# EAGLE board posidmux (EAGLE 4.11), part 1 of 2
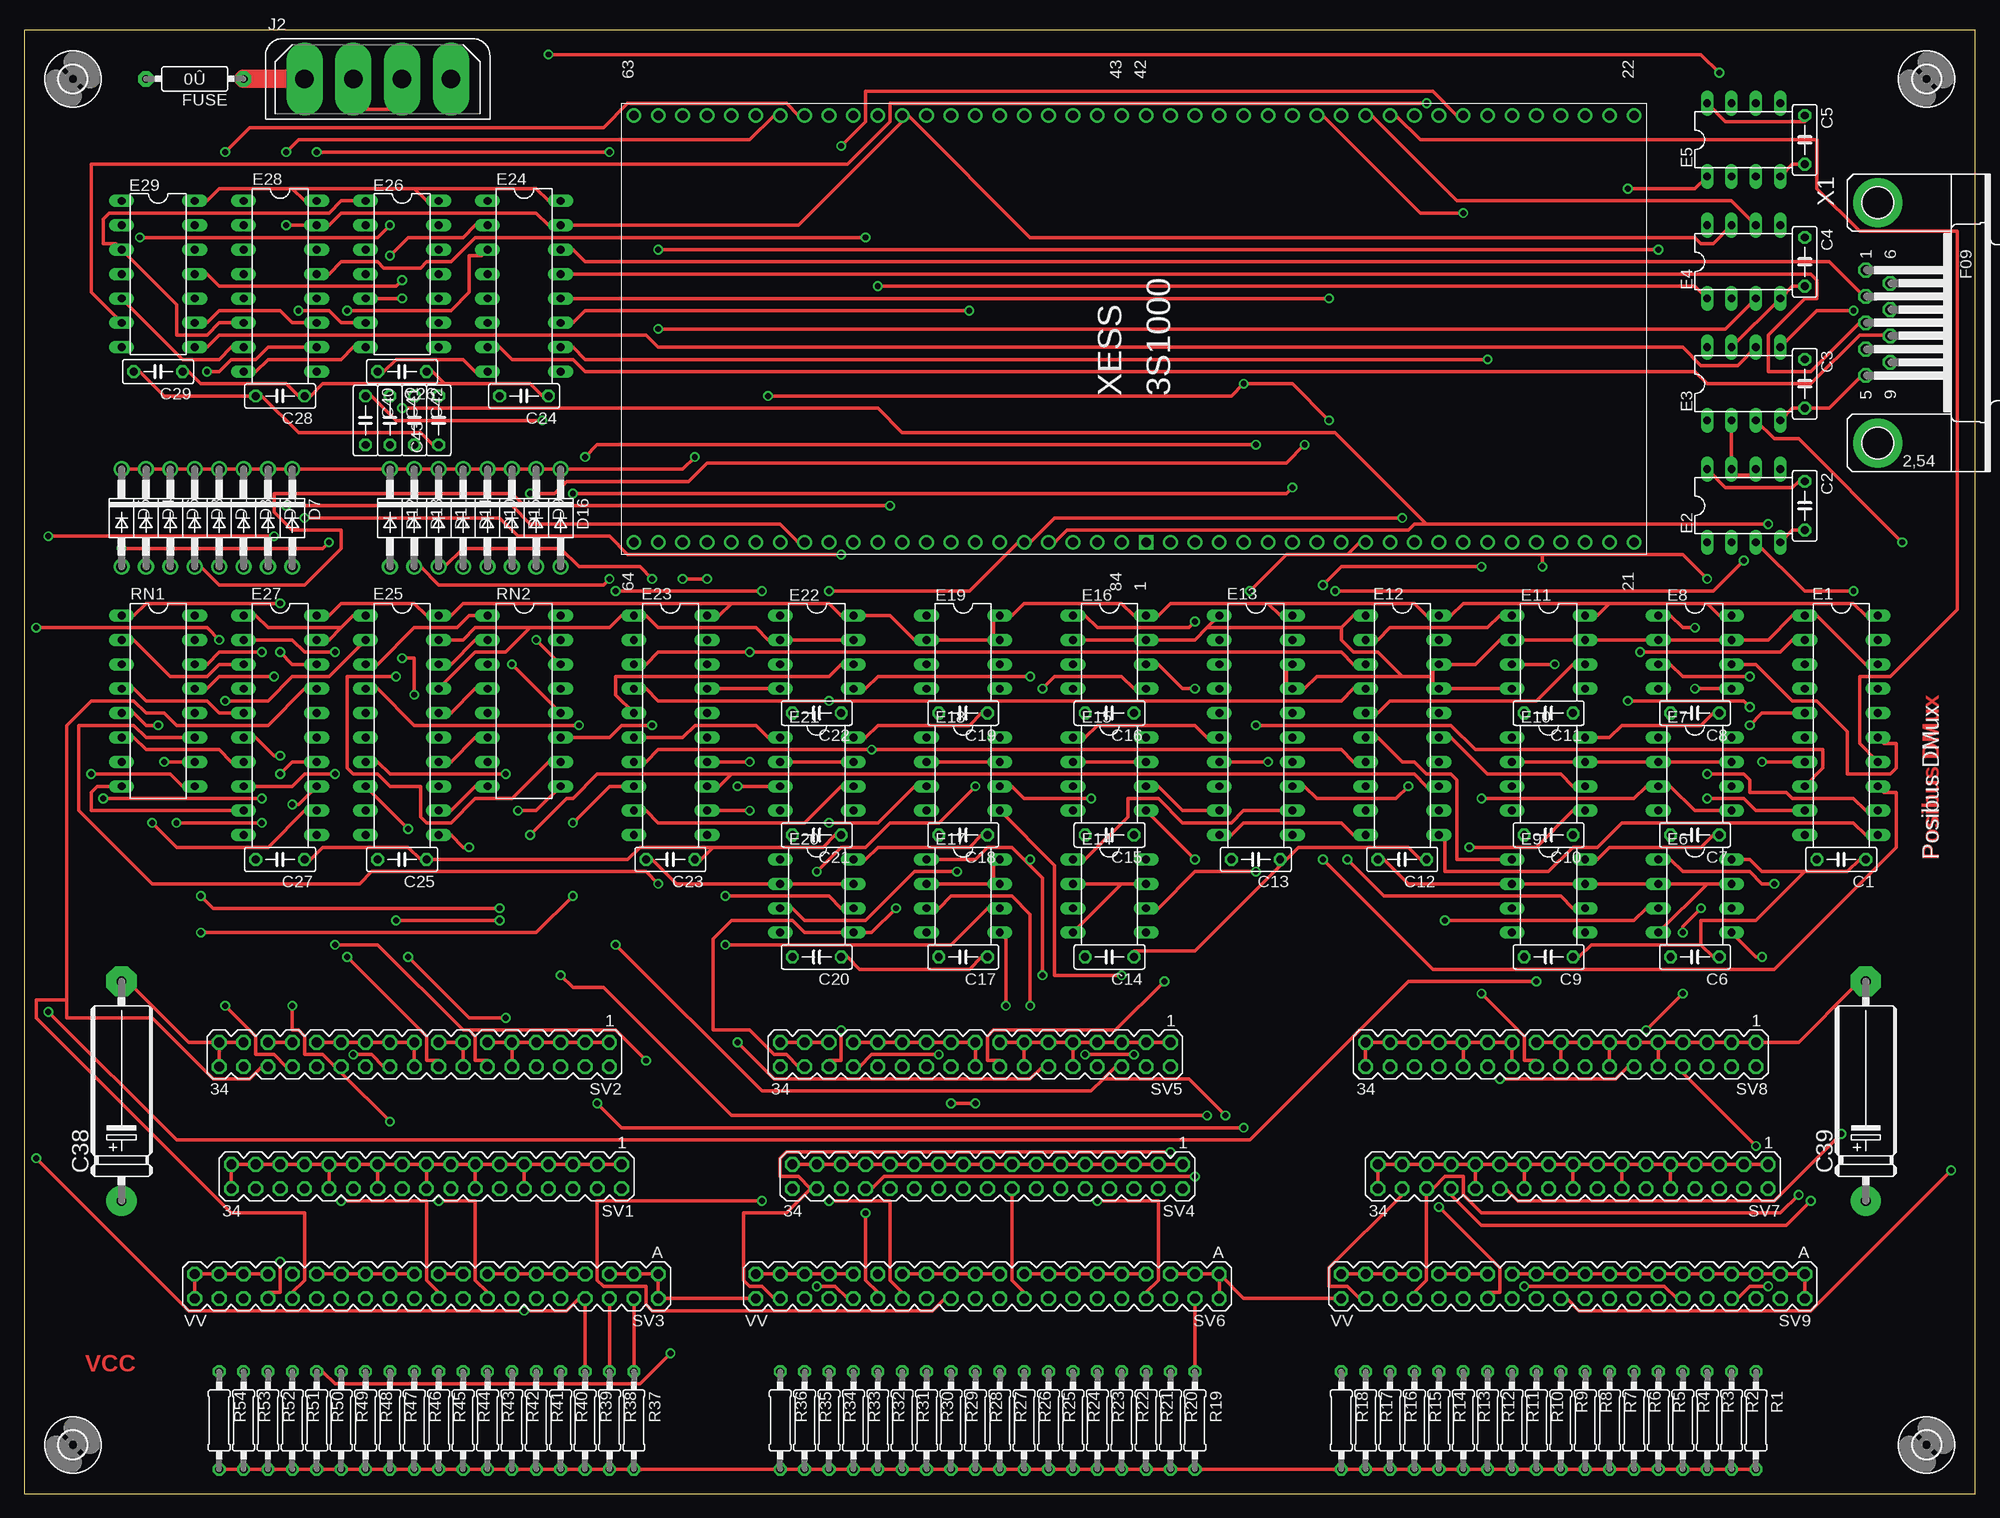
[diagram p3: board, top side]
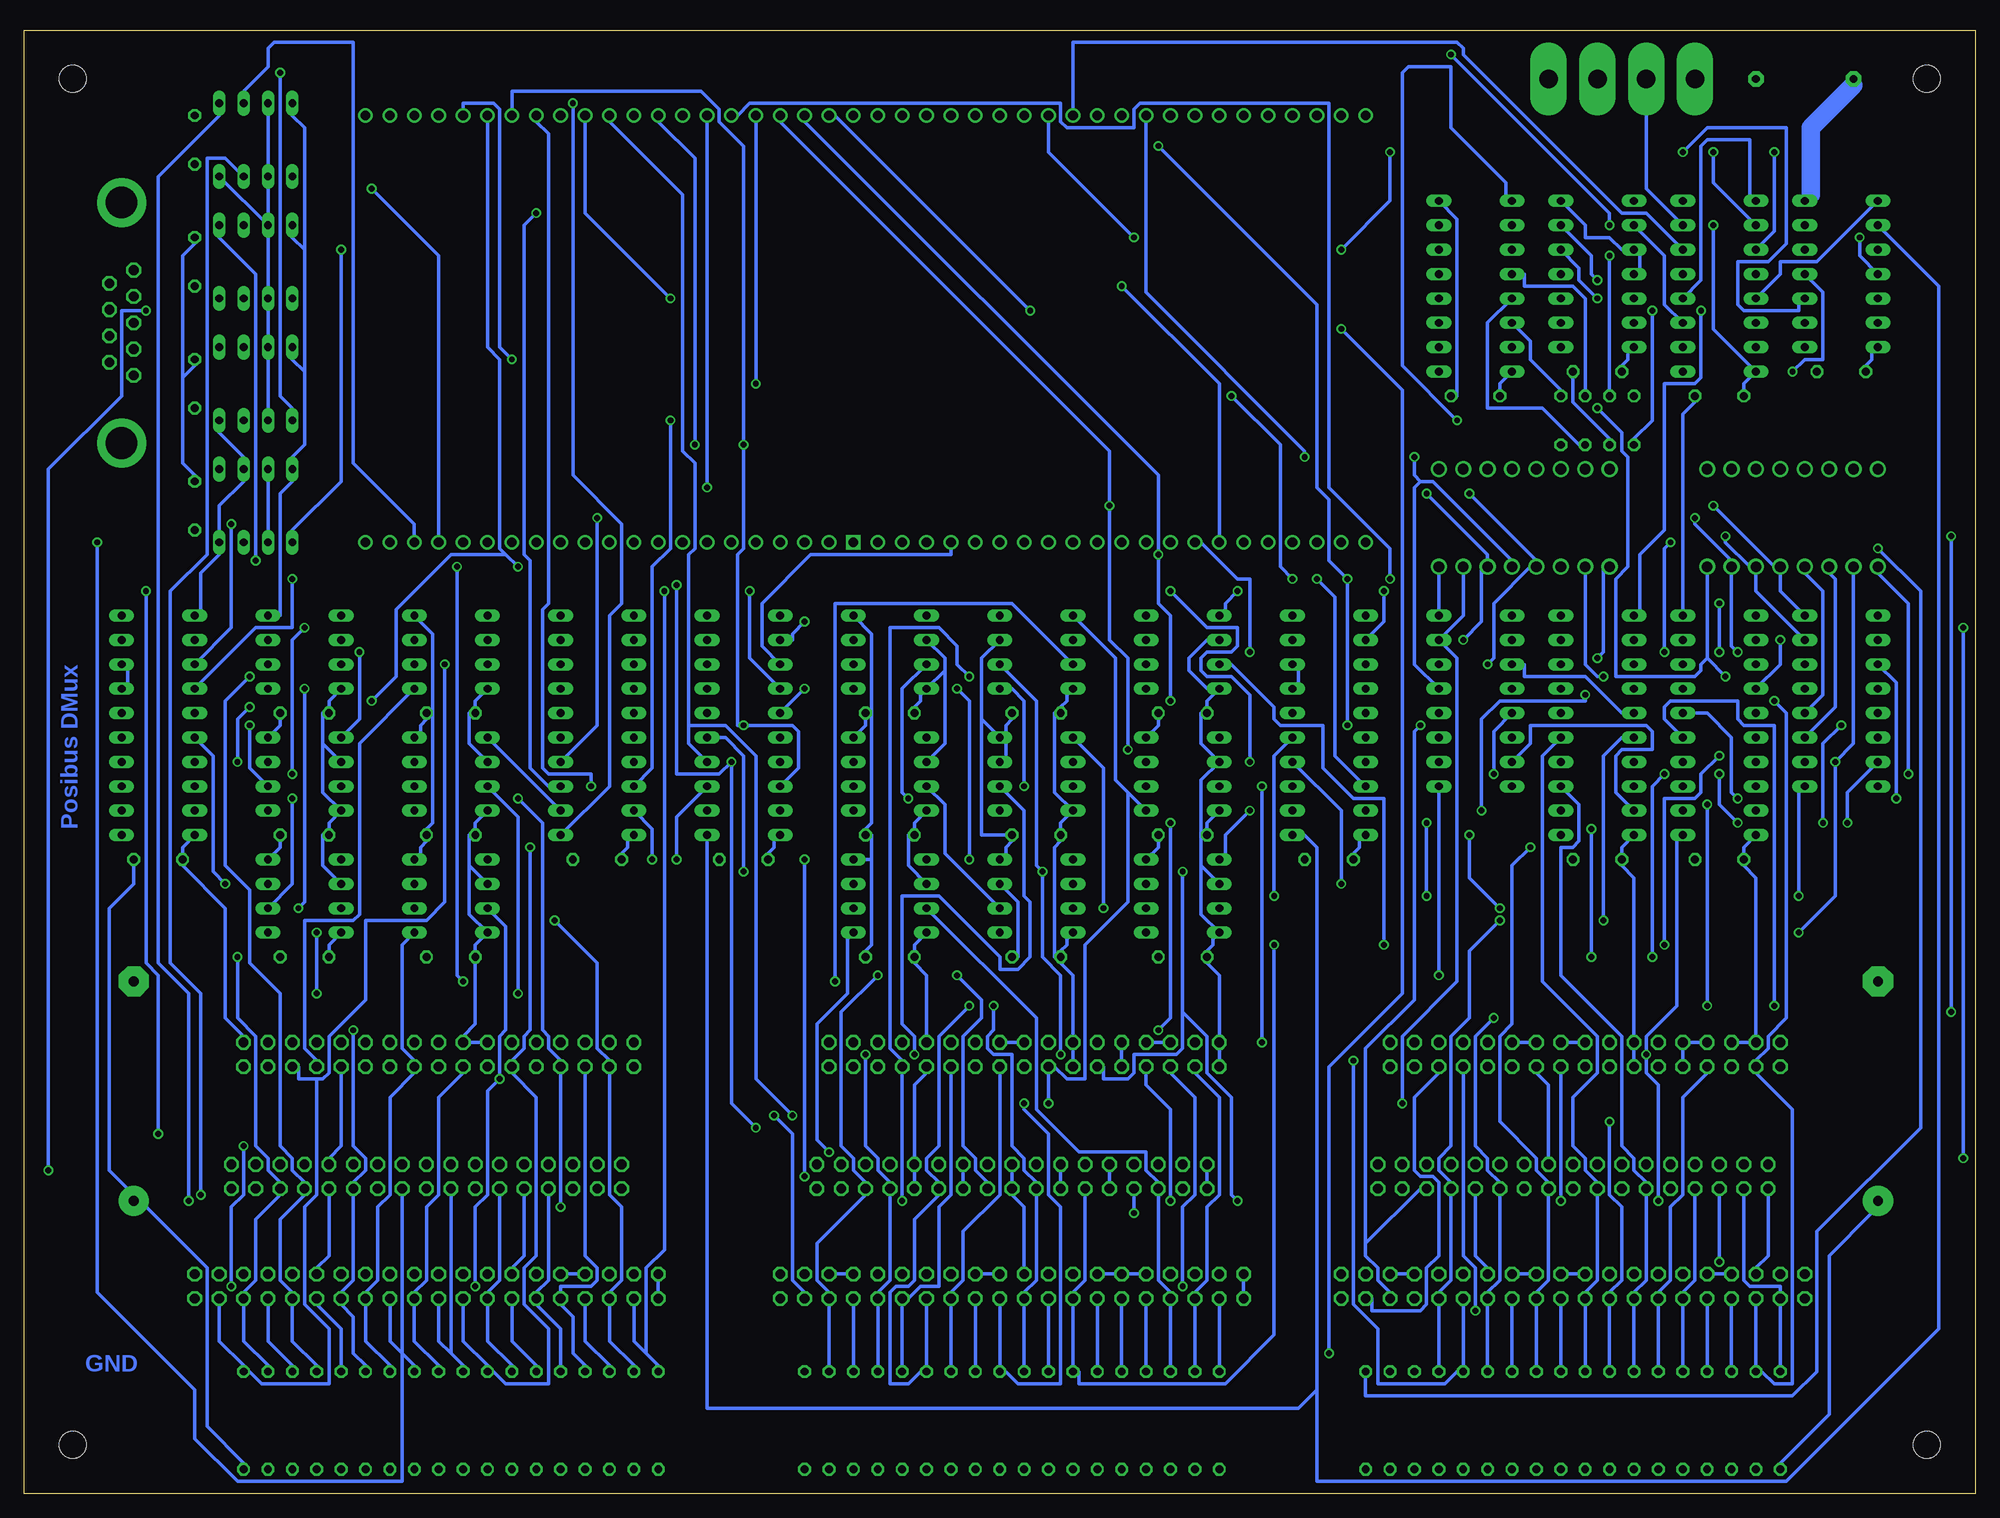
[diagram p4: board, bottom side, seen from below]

Size 203.2 x 152.4 mm. Coordinates in mm from the lower left corner, seen from the top.
Outline: 0,0 203.2,0 203.2,152.4 0,152.4 0,0
Copper layers (1*16): Top 0.035mm / dielectric 1.5mm / Bottom 0.035mm
Design rules "olimex10mil": minimum track width 15mil, minimum drill 24mil, track to track 15mil, track to pad 10mil, pad to pad 10mil, via to via 10mil, smd to smd 10mil, copper to edge 25mil, drill to drill 10mil, minimum pad ring 10mil, minimum via ring 8mil, stop-mask expansion 0mil, vias tented up to drill 0mil, thermal gap 10mil
Net classes: 1 Supply: width 1.905 mm, drill 0.508 mm

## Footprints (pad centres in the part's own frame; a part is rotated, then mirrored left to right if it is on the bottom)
C050-025X075 = drill 0.813 octagon: 1 -2.54,0; 2 2.54,0
E22-6 = drill 1.016 pad 3.15 round: + -11.43,0 | drill 1.016 pad 3.15 octagon: - 11.43,0
DO41-10 = drill 1.118 round: A 5.08,0; C -5.08,0
DIL20 = drill 0.813 long: 1 -11.43,-3.81; 2 -8.89,-3.81; 3 -6.35,-3.81; 4 -3.81,-3.81; 5 -1.27,-3.81; 6 1.27,-3.81; 7 3.81,-3.81; 8 6.35,-3.81; 9 8.89,-3.81; 10 11.43,-3.81; 11 11.43,3.81; 12 8.89,3.81; 13 6.35,3.81; 14 3.81,3.81; 15 1.27,3.81; 16 -1.27,3.81; 17 -3.81,3.81; 18 -6.35,3.81; 19 -8.89,3.81; 20 -11.43,3.81
DIL08 = drill 0.813 long: 1 -3.81,-3.81; 2 -1.27,-3.81; 3 1.27,-3.81; 4 3.81,-3.81; 5 3.81,3.81; 6 1.27,3.81; 7 -1.27,3.81; 8 -3.81,3.81
DIL16 = drill 0.813 long: 1 -8.89,-3.81; 2 -6.35,-3.81; 3 -3.81,-3.81; 4 -1.27,-3.81; 5 1.27,-3.81; 6 3.81,-3.81; 7 6.35,-3.81; 8 8.89,-3.81; 9 8.89,3.81; 10 6.35,3.81; 11 3.81,3.81; 12 1.27,3.81; 13 -1.27,3.81; 14 -3.81,3.81; 15 -6.35,3.81; 16 -8.89,3.81
DIL14 = drill 0.813 long: 1 -7.62,-3.81; 2 -5.08,-3.81; 3 -2.54,-3.81; 4 0,-3.81; 5 2.54,-3.81; 6 5.08,-3.81; 7 7.62,-3.81; 8 7.62,3.81; 9 5.08,3.81; 10 2.54,3.81; 11 0,3.81; 12 -2.54,3.81; 13 -5.08,3.81; 14 -7.62,3.81
0R/10 = drill 0.813 pad 1.6 octagon: 1 -5.08,0; 2 5.08,0
FLOPPY-4 = drill 1.93 pad 3.81 long: 1 7.62,0; 2 2.54,0; 3 -2.54,0; 4 -7.62,0
0207/10 = drill 0.813 octagon: 1 -5.08,0; 2 5.08,0
MA17-2 = drill 1.016 octagon: 1 -20.32,-1.27; 2 -20.32,1.27; 3 -17.78,-1.27; 4 -17.78,1.27; 5 -15.24,-1.27; 6 -15.24,1.27; 7 -12.7,-1.27; 8 -12.7,1.27; 9 -10.16,-1.27; 10 -10.16,1.27; 11 -7.62,-1.27; 12 -7.62,1.27; 13 -5.08,-1.27; 14 -5.08,1.27; 15 -2.54,-1.27; 16 -2.54,1.27; 17 0,-1.27; 18 0,1.27; 19 2.54,-1.27; 20 2.54,1.27; 21 5.08,-1.27; 22 5.08,1.27; 23 7.62,-1.27; 24 7.62,1.27; 25 10.16,-1.27; 26 10.16,1.27; 27 12.7,-1.27; 28 12.7,1.27; 29 15.24,-1.27; 30 15.24,1.27; 31 17.78,-1.27; 32 17.78,1.27; 33 20.32,-1.27; 34 20.32,1.27
DEC40PIN = drill 1.016 octagon: A -24.13,-1.27; AA 3.81,-1.27; B -24.13,1.27; BB 3.81,1.27; C -21.59,-1.27; CC 6.35,-1.27; D -21.59,1.27; DD 6.35,1.27; E -19.05,-1.27; EE 8.89,-1.27; F -19.05,1.27; FF 8.89,1.27; H -16.51,-1.27; HH 11.43,-1.27; J -16.51,1.27; JJ 11.43,1.27; K -13.97,-1.27; KK 13.97,-1.27; L -13.97,1.27; LL 13.97,1.27; M -11.43,-1.27; MM 16.51,-1.27; N -11.43,1.27; NN 16.51,1.27; P -8.89,-1.27; PP 19.05,-1.27; R -8.89,1.27; RR 19.05,1.27; S -6.35,-1.27; SS 21.59,-1.27; T -6.35,1.27; TT 21.59,1.27; U -3.81,-1.27; UU 24.13,-1.27; V -3.81,1.27; VV 24.13,1.27; W -1.27,-1.27; X -1.27,1.27; Y 1.27,-1.27; Z 1.27,1.27
2,8 = hole 2.8: 0,0
F09HP = drill 1.016 octagon: 1 -5.486,-1.27; 2 -2.743,-1.27; 3 0,-1.27; 4 2.743,-1.27; 5 5.486,-1.27; 6 -4.115,1.27; 7 -1.372,1.27; 8 1.372,1.27; 9 4.115,1.27 | drill 3.302 pad 5.08 round: G1 -12.522,0; G2 12.522,0
3S1000 = drill 1.016 square: 1 0,0 | drill 1.016 round: 2 0,-2.54; 3 0,-5.08; 4 0,-7.62; 5 0,-10.16; 6 0,-12.7; 7 0,-15.24; 8 0,-17.78; 9 0,-20.32; 10 0,-22.86; 11 0,-25.4; 12 0,-27.94; 13 0,-30.48; 14 0,-33.02; 15 0,-35.56; 16 0,-38.1; 17 0,-40.64; 18 0,-43.18; 19 0,-45.72; 20 0,-48.26; 21 0,-50.8; 22 44.45,-50.8; 23 44.45,-48.26; 24 44.45,-45.72; 25 44.45,-43.18; 26 44.45,-40.64; 27 44.45,-38.1; 28 44.45,-35.56; 29 44.45,-33.02; 30 44.45,-30.48; 31 44.45,-27.94; 32 44.45,-25.4; 33 44.45,-22.86; 34 44.45,-20.32; 35 44.45,-17.78; 36 44.45,-15.24; 37 44.45,-12.7; 38 44.45,-10.16; 39 44.45,-7.62; 40 44.45,-5.08; 41 44.45,-2.54; 42 44.45,0; 43 44.45,2.54; 44 44.45,5.08; 45 44.45,7.62; 46 44.45,10.16; 47 44.45,12.7; 48 44.45,15.24; 49 44.45,17.78; 50 44.45,20.32; 51 44.45,22.86; 52 44.45,25.4; 53 44.45,27.94; 54 44.45,30.48; 55 44.45,33.02; 56 44.45,35.56; 57 44.45,38.1; 58 44.45,40.64; 59 44.45,43.18; 60 44.45,45.72; 61 44.45,48.26; 62 44.45,50.8; 63 44.45,53.34; 64 0,53.34; 65 0,50.8; 66 0,48.26; 67 0,45.72; 68 0,43.18; 69 0,40.64; 70 0,38.1; 71 0,35.56; 72 0,33.02; 73 0,30.48; 74 0,27.94; 75 0,25.4; 76 0,22.86; 77 0,20.32; 78 0,17.78; 79 0,15.24; 80 0,12.7; 81 0,10.16; 82 0,7.62; 83 0,5.08; 84 0,2.54

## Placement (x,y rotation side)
C1  [C050-025X075]  189.23,66.04 180 top
C2  [C050-025X075]  185.42,102.87 270 top
C3  [C050-025X075]  185.42,115.57 270 top
C4  [C050-025X075]  185.42,128.27 270 top
C5  [C050-025X075]  185.42,140.97 270 top
C6  [C050-025X075]  173.99,55.88 180 top
C7  [C050-025X075]  173.99,68.58 180 top
C8  [C050-025X075]  173.99,81.28 180 top
C9  [C050-025X075]  158.75,55.88 180 top
C10  [C050-025X075]  158.75,68.58 180 top
C11  [C050-025X075]  158.75,81.28 180 top
C12  [C050-025X075]  143.51,66.04 180 top
C13  [C050-025X075]  128.27,66.04 180 top
C14  [C050-025X075]  113.03,55.88 180 top
C15  [C050-025X075]  113.03,68.58 180 top
C16  [C050-025X075]  113.03,81.28 180 top
C17  [C050-025X075]  97.79,55.88 180 top
C18  [C050-025X075]  97.79,68.58 180 top
C19  [C050-025X075]  97.79,81.28 180 top
C20  [C050-025X075]  82.55,55.88 180 top
C21  [C050-025X075]  82.55,68.58 180 top
C22  [C050-025X075]  82.55,81.28 180 top
C23  [C050-025X075]  67.31,66.04 180 top
C24  [C050-025X075]  52.07,114.3 180 top
C25  [C050-025X075]  39.37,66.04 180 top
C26  [C050-025X075]  39.37,116.84 180 top
C27  [C050-025X075]  26.67,66.04 180 top
C28  [C050-025X075]  26.67,114.3 180 top
C29  [C050-025X075]  13.97,116.84 180 top
C38  [E22-6]  10.16,41.91 90 top
C39  [E22-6]  191.77,41.91 90 top
C40  [C050-025X075]  35.56,111.76 270 top
C41  [C050-025X075]  38.1,111.76 270 top
C42  [C050-025X075]  40.64,111.76 270 top
C43  [C050-025X075]  43.18,111.76 90 top
D1  1N4004  [DO41-10]  20.32,101.6 270 top
D2  1N4004  [DO41-10]  25.4,101.6 270 top
D3  1N4004  [DO41-10]  17.78,101.6 270 top
D4  1N4004  [DO41-10]  12.7,101.6 270 top
D5  1N4004  [DO41-10]  10.16,101.6 270 top
D6  1N4004  [DO41-10]  15.24,101.6 270 top
D7  1N4004  [DO41-10]  27.94,101.6 270 top
D8  1N4004  [DO41-10]  22.86,101.6 270 top
D9  1N4004  [DO41-10]  53.34,101.6 270 top
D10  1N4004  [DO41-10]  48.26,101.6 270 top
D11  1N4004  [DO41-10]  43.18,101.6 270 top
D12  1N4004  [DO41-10]  38.1,101.6 270 top
D13  1N4004  [DO41-10]  40.64,101.6 270 top
D14  1N4004  [DO41-10]  45.72,101.6 270 top
D15  1N4004  [DO41-10]  50.8,101.6 270 top
D16  1N4004  [DO41-10]  55.88,101.6 270 top
E1  74HCT373N  [DIL20]  189.23,80.01 270 top
E2  DS75453N  [DIL08]  179.07,102.87 0 top
E3  DS75453N  [DIL08]  179.07,115.57 0 top
E4  DS75453N  [DIL08]  179.07,128.27 0 top
E5  DS75453N  [DIL08]  179.07,140.97 0 top
E6  DS75453N  [DIL08]  173.99,62.23 270 top
E7  DS75453N  [DIL08]  173.99,74.93 270 top
E8  DS75453N  [DIL08]  173.99,87.63 270 top
E9  DS75453N  [DIL08]  158.75,62.23 270 top
E10  DS75453N  [DIL08]  158.75,74.93 270 top
E11  DS75453N  [DIL08]  158.75,87.63 270 top
E12  74HCT373N  [DIL20]  143.51,80.01 270 top
E13  74HCT373N  [DIL20]  128.27,80.01 270 top
E14  DS75453N  [DIL08]  113.03,62.23 270 top
E15  DS75453N  [DIL08]  113.03,74.93 270 top
E16  DS75453N  [DIL08]  113.03,87.63 270 top
E17  DS75452N  [DIL08]  97.79,62.23 270 top
E18  DS75452N  [DIL08]  97.79,74.93 270 top
E19  DS75452N  [DIL08]  97.79,87.63 270 top
E20  DS75453N  [DIL08]  82.55,62.23 270 top
E21  DS75453N  [DIL08]  82.55,74.93 270 top
E22  DS75453N  [DIL08]  82.55,87.63 270 top
E23  74HCT373N  [DIL20]  67.31,80.01 270 top
E24  MAX232  [DIL16]  52.07,125.73 270 top
E25  74HCT244N  [DIL20]  39.37,80.01 270 top
E26  74LS10N  [DIL14]  39.37,127 270 top
E27  74HCT244N  [DIL20]  26.67,80.01 270 top
E28  74HCT139N  [DIL16]  26.67,125.73 270 top
E29  74HCT04N  [DIL14]  13.97,127 270 top
FUSE  [0R/10]  17.78,147.32 180 top
J2  [FLOPPY-4]  36.83,147.32 0 top
R1  [0207/10]  180.34,7.62 270 top
R2  [0207/10]  177.8,7.62 270 top
R3  [0207/10]  175.26,7.62 270 top
R4  [0207/10]  172.72,7.62 270 top
R5  [0207/10]  170.18,7.62 270 top
R6  [0207/10]  167.64,7.62 270 top
R7  [0207/10]  165.1,7.62 270 top
R8  [0207/10]  162.56,7.62 270 top
R9  [0207/10]  160.02,7.62 270 top
R10  [0207/10]  157.48,7.62 270 top
R11  [0207/10]  154.94,7.62 270 top
R12  [0207/10]  152.4,7.62 270 top
R13  [0207/10]  149.86,7.62 270 top
R14  [0207/10]  147.32,7.62 270 top
R15  [0207/10]  144.78,7.62 270 top
R16  [0207/10]  142.24,7.62 270 top
R17  [0207/10]  139.7,7.62 270 top
R18  [0207/10]  137.16,7.62 270 top
R19  [0207/10]  121.92,7.62 270 top
R20  [0207/10]  119.38,7.62 270 top
R21  [0207/10]  116.84,7.62 270 top
R22  [0207/10]  114.3,7.62 270 top
R23  [0207/10]  111.76,7.62 270 top
R24  [0207/10]  109.22,7.62 270 top
R25  [0207/10]  106.68,7.62 270 top
R26  [0207/10]  104.14,7.62 270 top
R27  [0207/10]  101.6,7.62 270 top
R28  [0207/10]  99.06,7.62 270 top
R29  [0207/10]  96.52,7.62 270 top
R30  [0207/10]  93.98,7.62 270 top
R31  [0207/10]  91.44,7.62 270 top
R32  [0207/10]  88.9,7.62 270 top
R33  [0207/10]  86.36,7.62 270 top
R34  [0207/10]  83.82,7.62 270 top
R35  [0207/10]  81.28,7.62 270 top
R36  [0207/10]  78.74,7.62 270 top
R37  [0207/10]  63.5,7.62 270 top
R38  [0207/10]  60.96,7.62 270 top
R39  [0207/10]  58.42,7.62 270 top
R40  [0207/10]  55.88,7.62 270 top
R41  [0207/10]  53.34,7.62 270 top
R42  [0207/10]  50.8,7.62 270 top
R43  [0207/10]  48.26,7.62 270 top
R44  [0207/10]  45.72,7.62 270 top
R45  [0207/10]  43.18,7.62 270 top
R46  [0207/10]  40.64,7.62 270 top
R47  [0207/10]  38.1,7.62 270 top
R48  [0207/10]  35.56,7.62 270 top
R49  [0207/10]  33.02,7.62 270 top
R50  [0207/10]  30.48,7.62 270 top
R51  [0207/10]  27.94,7.62 270 top
R52  [0207/10]  25.4,7.62 270 top
R53  [0207/10]  22.86,7.62 270 top
R54  [0207/10]  20.32,7.62 270 top
RN1  330  [DIL16]  13.97,82.55 270 top
RN2  [DIL16]  52.07,82.55 270 top
SV1  [MA17-2]  41.91,33.02 180 top
SV2  [MA17-2]  40.64,45.72 180 top
SV3  [DEC40PIN]  41.91,21.59 180 top
SV4  [MA17-2]  100.33,33.02 180 top
SV5  [MA17-2]  99.06,45.72 180 top
SV6  [DEC40PIN]  100.33,21.59 180 top
SV7  [MA17-2]  161.29,33.02 180 top
SV8  [MA17-2]  160.02,45.72 180 top
SV9  [DEC40PIN]  161.29,21.59 180 top
U$1  [2,8]  198.12,5.08 0 top
U$2  [2,8]  5.08,147.32 0 top
U$3  [2,8]  198.12,147.32 0 top
U$4  [2,8]  5.08,5.08 0 top
X1  [F09HP]  193.04,121.92 270 top
XESS  3S1000  [3S1000]  116.84,99.06 90 top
